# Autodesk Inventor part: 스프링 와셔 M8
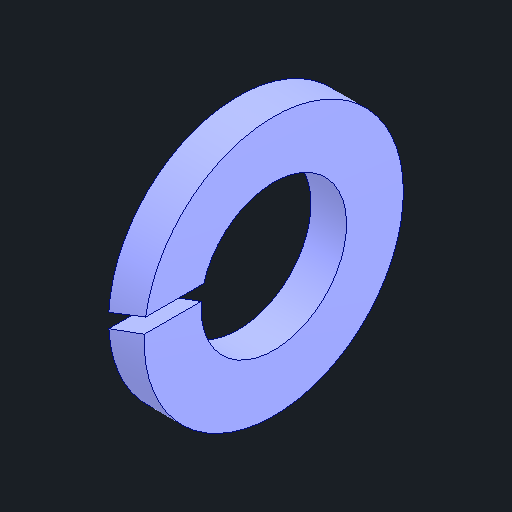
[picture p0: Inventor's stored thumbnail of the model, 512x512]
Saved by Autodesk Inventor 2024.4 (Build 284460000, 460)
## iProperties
Created: 2025-10
Part Number: 스프링 와셔 M8
Material: 강철, 연강
Description: 스프링 잠금 와셔
Document SubType Name: Modeling
Designer: user
Density: 7.85 g/cm^3
Appearance: 기본값
Author: jhkim
Sending System: Autodesk Inventor 2026
Preprocessor: ST-DEVELOPER v20.1
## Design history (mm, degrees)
feature "Solid1"
node "솔리드1"
